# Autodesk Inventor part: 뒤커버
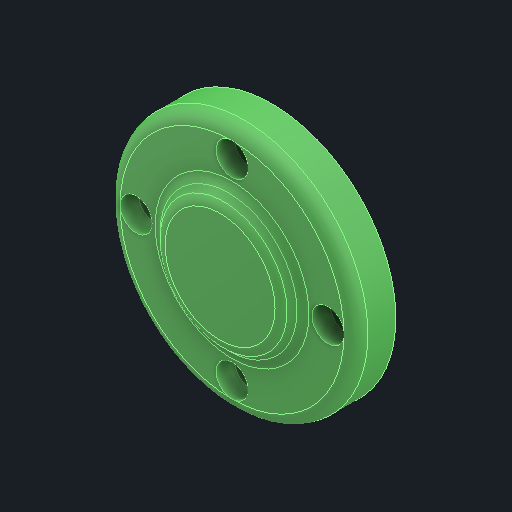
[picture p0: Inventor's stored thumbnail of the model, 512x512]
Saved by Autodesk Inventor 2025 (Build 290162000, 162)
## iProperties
Created: 2025-08
Part Number: 뒤커버
Material: 알루미늄 6061
Document SubType Name: Modeling
Designer: infra027
Density: 2.71 g/cm^3
Appearance: 기본값
Author: jhkim
Sending System: Autodesk Inventor 2026
Preprocessor: ST-DEVELOPER v20.1
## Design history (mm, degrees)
feature "솔리드1"
node "솔리드2"
